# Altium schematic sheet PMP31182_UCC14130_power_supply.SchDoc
size A3; Date: Not shown in title block; ApprovedBy: Not shown in title block; CheckedBy: Not shown in title block; Author: Not shown in title block; CompanyName: Not shown in title block; Engineer: Not shown in title block; Organization: Not shown in title block; Address1: Not shown in title block; Address2: Not shown in title block; Address3: Not shown in title block; Address4: Not shown in title block; DocumentNumber: UCC14130-Q1; Revision: Use project parameter SCH_Rev; SheetNumber: 1; SheetTotal: 1; PageSetup: Record=PageOptions¦CenterHorizontal=True¦CenterVertical=True¦PrintScale=0.69¦XCorrection=1.00¦YCorrection=1.00¦PrintKind=0¦BorderSize=5000000¦LeftOffset=0¦BottomOffset=0¦Orientation=2¦PaperLength=1000¦PaperWidth=1000¦Scale=100¦PaperSource=15¦PrintQuality=600¦MediaType=1¦DitherType=10¦PaperKind=Letter¦PrintScaleMode=1
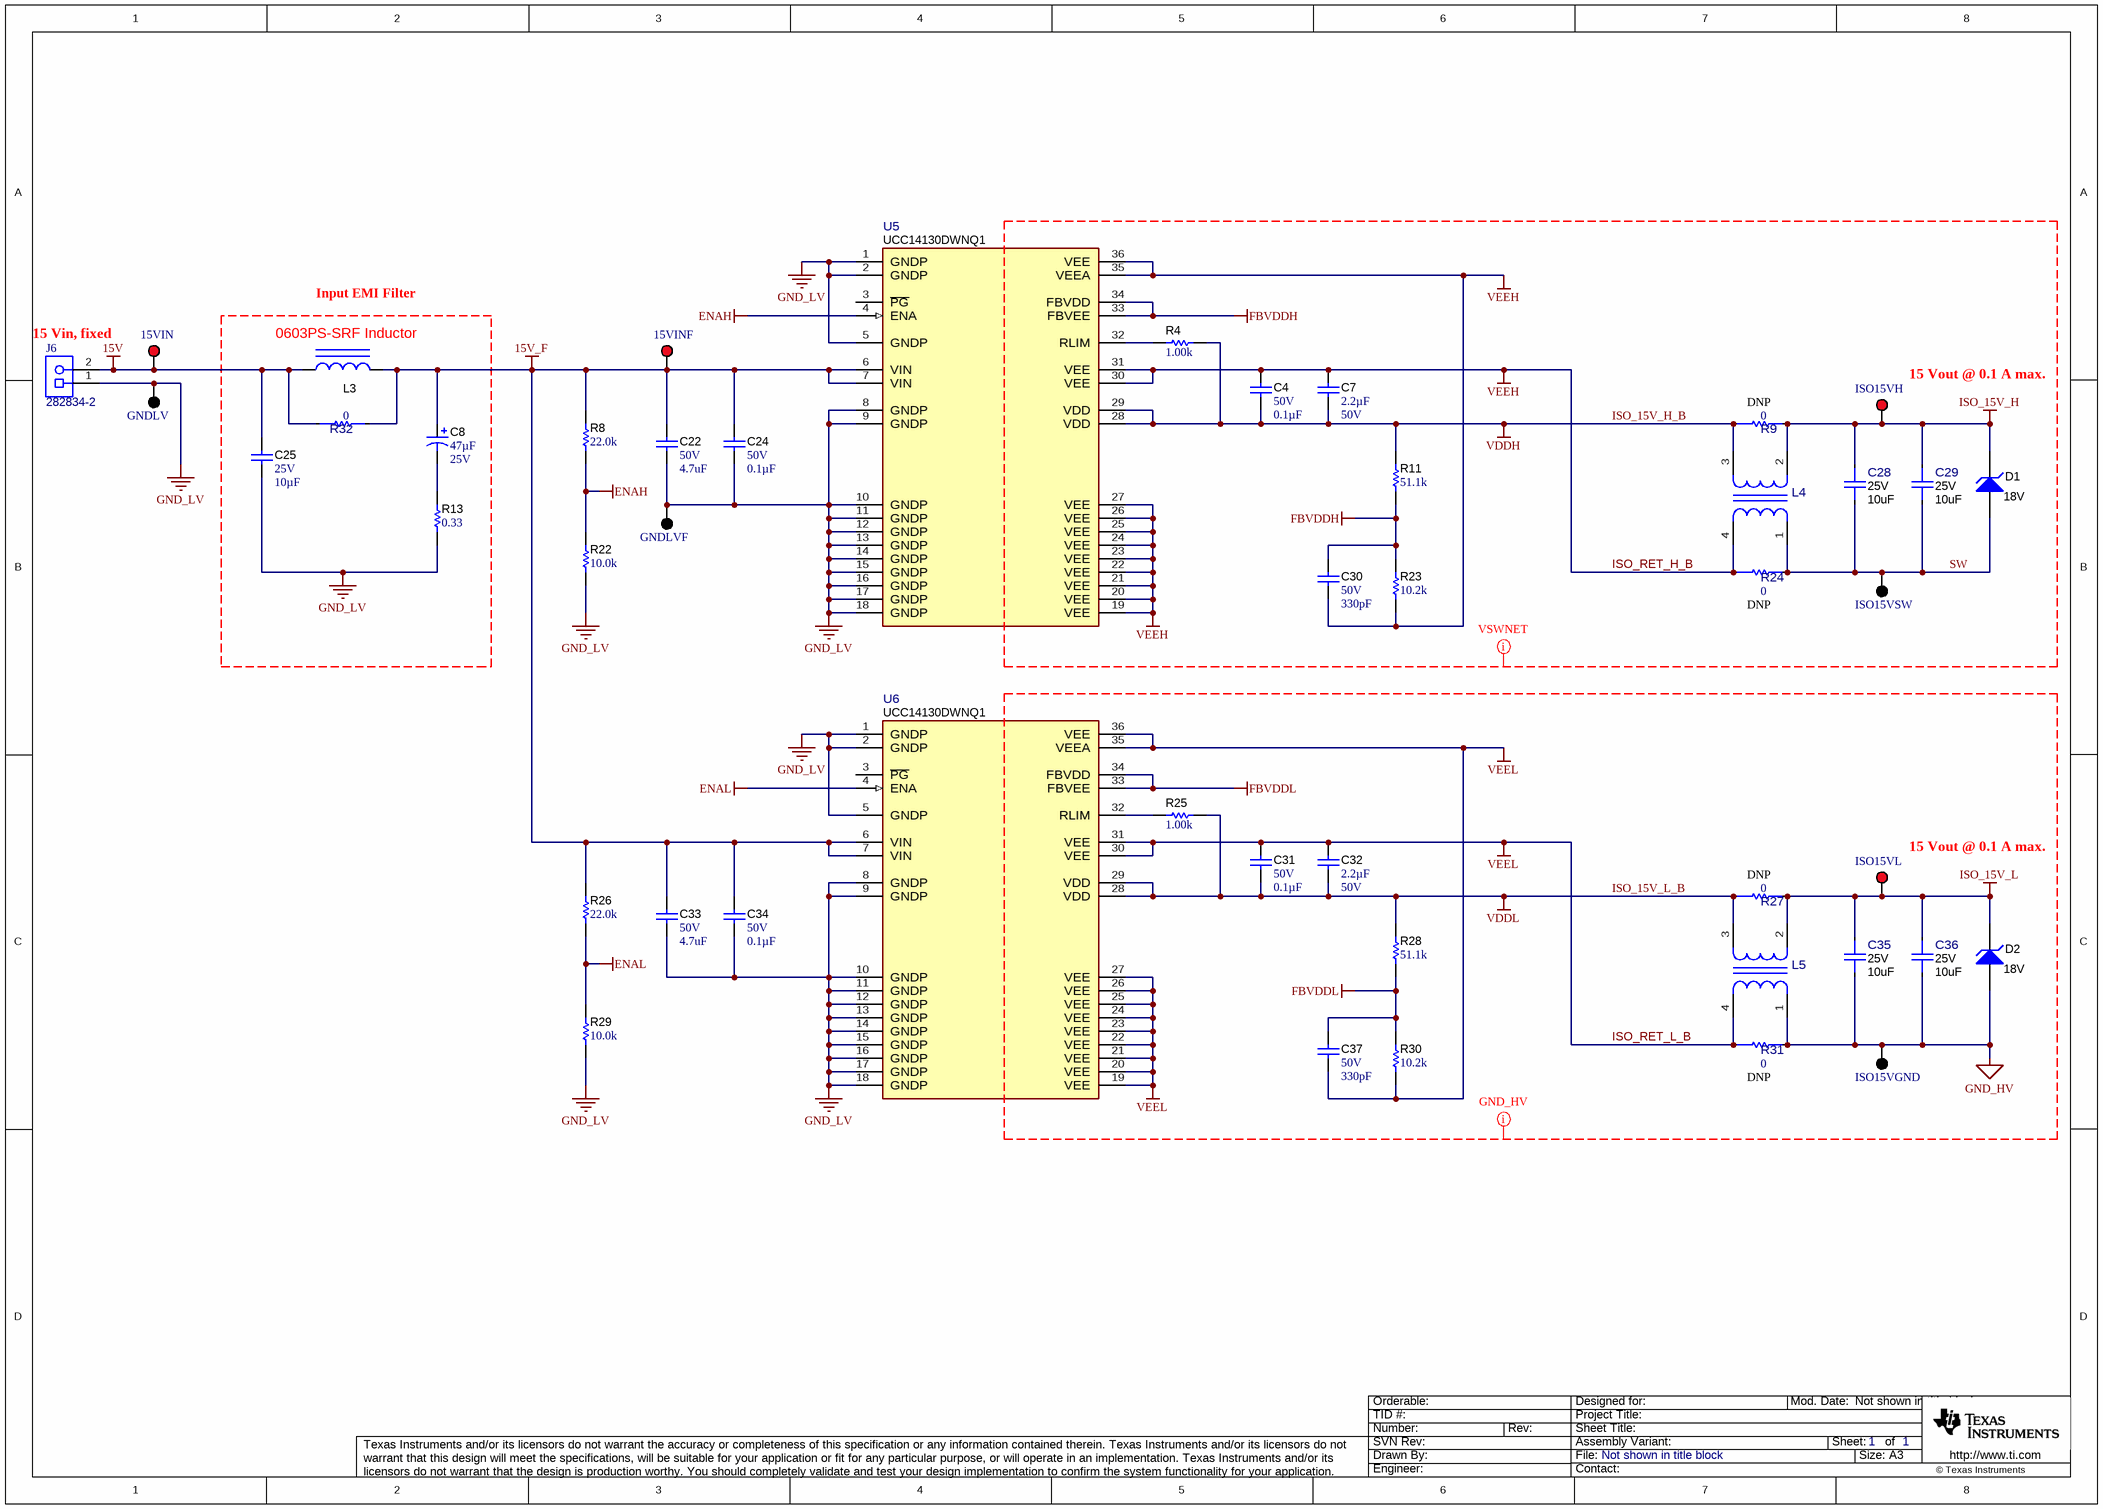
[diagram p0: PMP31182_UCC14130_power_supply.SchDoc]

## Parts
15VIN  5005  [Keystone5005]  (value not drawn)
15VINF  5005  [Keystone5005]  (value not drawn)
C4  VDC_V: 50V  ValueDisplayed: 0.1µF  [0603]  (hidden comment: CGA3E3X8R1H104K080AE)
C7  Cap_F: 2.2µF  VDC_V: 50V  [0805_HV]  (hidden comment: CGA4J3X7R1H225K125AB)
C8  ValueDisplayed: 47µF  VDC_V: 25V  [HXB_F61]  (hidden comment: HHXC250ARA470MF61G)
C22  VDC_V: 50V  ValueDisplayed: 4.7uF  [1210_280]  (hidden comment: CGA6P3X7R1H475M250AB)
C24  VDC_V: 50V  ValueDisplayed: 0.1µF  [0603]  (hidden comment: CGA3E3X8R1H104K080AE)
C25  VDC_V: 25V  ValueDisplayed: 10µF  [1206_180]  (hidden comment: C1206C106J3RACAUTO)
C28  VDC_V: 25V  ValueDisplayed: 10uF  [FP-CGA4J1X7S1E106K125AC_0805-MFG]  (hidden comment: CGA4J1X7S1E106K125AC)
C29  VDC_V: 25V  ValueDisplayed: 10uF  [FP-CGA4J1X7S1E106K125AC_0805-MFG]  (hidden comment: CGA4J1X7S1E106K125AC)
C30  VDC_V: 50V  ValueDisplayed: 330pF  [0603]  (hidden comment: 06035A331JAT2A)
C31  VDC_V: 50V  ValueDisplayed: 0.1µF  [0603]  (hidden comment: CGA3E3X8R1H104K080AE)
C32  Cap_F: 2.2µF  VDC_V: 50V  [0805_HV]  (hidden comment: CGA4J3X7R1H225K125AB)
C33  VDC_V: 50V  ValueDisplayed: 4.7uF  [1210_280]  (hidden comment: CGA6P3X7R1H475M250AB)
C34  VDC_V: 50V  ValueDisplayed: 0.1µF  [0603]  (hidden comment: CGA3E3X8R1H104K080AE)
C35  VDC_V: 25V  ValueDisplayed: 10uF  [FP-CGA4J1X7S1E106K125AC_0805-MFG]  (hidden comment: CGA4J1X7S1E106K125AC)
C36  VDC_V: 25V  ValueDisplayed: 10uF  [FP-CGA4J1X7S1E106K125AC_0805-MFG]  (hidden comment: CGA4J1X7S1E106K125AC)
C37  VDC_V: 50V  ValueDisplayed: 330pF  [0603]  (hidden comment: 06035A331JAT2A)
D1  value 18V  [SOD-123]  (hidden comment: BZT52C18-7-F)
D2  value 18V  [SOD-123]  (hidden comment: BZT52C18-7-F)
GNDLV  5006  [Keystone5006]  (value not drawn)
GNDLVF  5006  [Keystone5006]  (value not drawn)
ISO15VGND  5006  [Keystone5006]  (value not drawn)
ISO15VH  5005  [Keystone5005]  (value not drawn)
ISO15VL  5005  [Keystone5005]  (value not drawn)
ISO15VSW  5006  [Keystone5006]  (value not drawn)
J6  282834-2  [TEC_282834-2]
L3  0603PS-SRF Inductor  [0603AF]
L4  ACM2012-900-2P-T001  [FP-ACM2012-900-2P-T001_SMD4-MFG]  (value not drawn)
L5  ACM2012-900-2P-T001  [FP-ACM2012-900-2P-T001_SMD4-MFG]  (value not drawn)
R4  ValueDisplayed: 1.00k  [0603]  (hidden comment: RT0603BRD071KL)
R8  ValueDisplayed: 22.0k  [0603]  (hidden comment: RC0603FR-0722KL)
R9  Res_ohm: 0  [FP-ERJ-3GEY0R00V_0603-MFG]  (hidden comment: ERJ-3GEY0R00V)
R11  ValueDisplayed: 51.1k  [0603]  (hidden comment: RT0603BRD0751K1L)
R13  ValueDisplayed: 0.33  [0603]  (hidden comment: ERJ-3RQFR33V)
R22  ValueDisplayed: 10.0k  [0603]  (hidden comment: ERJ-3EKF1002V)
R23  ValueDisplayed: 10.2k  [0603]  (hidden comment: RT0603DRE0710K2L)
R24  Res_ohm: 0  [FP-ERJ-3GEY0R00V_0603-MFG]  (hidden comment: ERJ-3GEY0R00V)
R25  ValueDisplayed: 1.00k  [0603]  (hidden comment: RT0603BRD071KL)
R26  ValueDisplayed: 22.0k  [0603]  (hidden comment: RC0603FR-0722KL)
R27  Res_ohm: 0  [FP-ERJ-3GEY0R00V_0603-MFG]  (hidden comment: ERJ-3GEY0R00V)
R28  ValueDisplayed: 51.1k  [0603]  (hidden comment: RT0603BRD0751K1L)
R29  ValueDisplayed: 10.0k  [0603]  (hidden comment: ERJ-3EKF1002V)
R30  ValueDisplayed: 10.2k  [0603]  (hidden comment: RT0603DRE0710K2L)
R31  Res_ohm: 0  [FP-ERJ-3GEY0R00V_0603-MFG]  (hidden comment: ERJ-3GEY0R00V)
R32  Res_ohm: 0  [FP-ERJ-3GEY0R00V_0603-MFG]  (hidden comment: ERJ-3GEY0R00V)
U5  PartNumber: UCC14130DWNQ1  [DWN0036-MFG]  (hidden comment: UCC14240DWNQ1)
U6  PartNumber: UCC14130DWNQ1  [DWN0036-MFG]  (hidden comment: UCC14240DWNQ1)

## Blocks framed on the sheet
Input EMI Filter: C8 C25 L3 R13 R32

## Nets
15V: 15VIN.1 C25.1 J6.2 L3.1 R32.1
15V_F: 15VINF.1 C8.1(+) C22.1 C24.1 C33.1 C34.1 L3.2 R8.2 R26.2 R32.2 U5.6(VIN) U5.7(VIN) U6.6(VIN) U6.7(VIN)
ENAH: R8.1 R22.2 U5.4(ENA)
ENAL: R26.1 R29.2 U6.4(ENA)
FBVDDH: C30.1 R11.1 R23.2 U5.33(FBVEE) U5.34(FBVDD)
FBVDDL: C37.1 R28.1 R30.2 U6.33(FBVEE) U6.34(FBVDD)
GND_HV: C35.2 C36.2 D2.2(A) ISO15VGND.1 L5.1 R31.2
GND_LV: C22.2 C24.2 C25.2 C33.2 C34.2 GNDLV.1 GNDLVF.1 J6.1 R13.1 R22.1 R29.1 U5.1(GNDP) U5.2(GNDP) U5.5(GNDP) U5.8(GNDP) U5.9(GNDP) U5.10(GNDP) U5.11(GNDP) U5.12(GNDP) U5.13(GNDP) U5.14(GNDP) U5.15(GNDP) U5.16(GNDP) U5.17(GNDP) U5.18(GNDP) U6.1(GNDP) U6.2(GNDP) U6.5(GNDP) U6.8(GNDP) U6.9(GNDP) U6.10(GNDP) U6.11(GNDP) U6.12(GNDP) U6.13(GNDP) U6.14(GNDP) U6.15(GNDP) U6.16(GNDP) U6.17(GNDP) U6.18(GNDP)
ISO_15V_H: C28.1 C29.1 D1.1(K) ISO15VH.1 L4.2 R9.2
ISO_15V_H_B: C4.2 C7.2 L4.3 R4.2 R9.1 R11.2 U5.28(VDD) U5.29(VDD)  [also labelled VDDH]
ISO_15V_L: C35.1 C36.1 D2.1(K) ISO15VL.1 L5.2 R27.2
ISO_15V_L_B: C31.2 C32.2 L5.3 R25.2 R27.1 R28.2 U6.28(VDD) U6.29(VDD)  [also labelled VDDL]
ISO_RET_H_B: C4.1 C7.1 C30.2 L4.4 R23.1 R24.1 U5.19(VEE) U5.20(VEE) U5.21(VEE) U5.22(VEE) U5.23(VEE) U5.24(VEE) U5.25(VEE) U5.26(VEE) U5.27(VEE) U5.30(VEE) U5.31(VEE) U5.35(VEEA) U5.36(VEE)  [also labelled VEEH]
ISO_RET_L_B: C31.1 C32.1 C37.2 L5.4 R30.1 R31.1 U6.19(VEE) U6.20(VEE) U6.21(VEE) U6.22(VEE) U6.23(VEE) U6.24(VEE) U6.25(VEE) U6.26(VEE) U6.27(VEE) U6.30(VEE) U6.31(VEE) U6.35(VEEA) U6.36(VEE)  [also labelled VEEL]
SW: C28.2 C29.2 D1.2(A) ISO15VSW.1 L4.1 R24.2
NetC8_2: C8.2(-) R13.2
NetR4_1: R4.1 U5.32(RLIM)
NetR25_1: R25.1 U6.32(RLIM)

Not connected (* = marked no-connect by the designer): U5 3(~{PG}); U6 3(~{PG})

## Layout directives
net class VSWNET: FBVDDH, ISO_15V_H, ISO_15V_H_B, ISO_RET_H_B, SW, VDDH, VEEH
net class PGND: FBVDDL, GND_HV, ISO_15V_L, ISO_15V_L_B, ISO_RET_L_B, VDDL, VEEL

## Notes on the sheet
- 15 Vin, fixed
- (near ISO15VH) 15 Vout @ 0.1 A max.
- (near R9) DNP
- (near R24) DNP
- (near ISO15VL) 15 Vout @ 0.1 A max.
- (near R27) DNP
- (near R31) DNP

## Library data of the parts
15VIN = CMP-0055142-2: Test Point, Compact, Red, TH; Manufacturer: Keystone Electronics; CNHeader: FALSE; Green_Lifecycle: Active; Green_REACh: Passed; ContactFinish: Silver; CT: TRUE
15VINF ISO15VH ISO15VL = CMP-0055142-1: Test Point, Compact, Red, TH; Manufacturer: Keystone; CNHeader: FALSE; Green_Lifecycle: Active; Green_REACh: Passed; ContactFinish: Silver; CT: TRUE
C4 C24 C31 C34 = CMP-0079911-1: CAP, CERM, 0.1 µF, 50 V,+/- 10%, X8R, AEC-Q200 Grade 0, 0603; Manufacturer: TDK; Cap_F: 100nF; SizeAreaWB_mm2: 4.68; SizeArea_mm2: 1.28; AEC Qualified: Y; AEC Category: Q200; Value: 0.1uF; TaMax_C: 150°C; SizeZ_mm: 1; AEC Grade: 0; Polarized: N; TaMin_C: -55°C; SizeY_mm: 0.8; U/M: EA; SizeX_mm: 1.6
C7 C32 = CMP-0007977-2: CAP, CERM, 2.2 uF, 50 V, +/- 10%, X7R, AEC-Q200 Grade 1, 0805; Manufacturer: TDK; TaMin_C: -55°C; ESR_ohm: 3.288m; Polarized: N; SizeAreaWB_mm2: 6.75; Value1: 0.003288 ohm; U/M: EA; Value: 2.2uF; TaMax_C: 125°C; SizeZ_mm: 1.45; SizeX_mm: 2; SizeY_mm: 1.25; Cap_Case: 0805; SizeArea_mm2: 2.5; AEC Qualified: Y; IRMS_A: 3.60029A; AEC Grade: 1; AEC Category: Q200
C8 = CMP-0750159-1: CAP, AL, 47 µF, 25 V, +/- 20%, 0.05 ohm, AEC-Q200 Grade 1, SMD; Manufacturer: Chemi-Con; TaMin_C: -55°C; Cap_Case: 6.3x5.8mm; CompType: Capacitor; TaMax_C: 125°C; U/M: EA; Value: 47uF; AEC Grade: 1; AEC Category: Q200; AEC Qualified: Y; ESR_ohm: 0.05
C22 C33 = CMP-0009163-2: CAP, CERM, 4.7 uF, 50 V, +/- 20%, X7R, AEC-Q200 Grade 1, 1210; Manufacturer: TDK; TaMin_C: -55°C; Polarized: N; SizeAreaWB_mm2: 14.7; Value1: Unknown; U/M: EA; Value: 4.7uF; TaMax_C: 125°C; SizeZ_mm: 2.8; SizeX_mm: 3.2; SizeY_mm: 2.5; Cap_Case: 1210; SizeArea_mm2: 8; AEC Qualified: Y; Cap_F: 4.7µF; AEC Grade: 1; AEC Category: Q200
C25 = CMP-0081062-1: CAP, CERM, 10 µF, 25 V,+/- 5%, X7R, AEC-Q200 Grade 1, 1206; Manufacturer: Kemet; TaMin_C: -55°C; Polarized: N; SizeAreaWB_mm2: 10.92; U/M: EA; Value: 10uF; TaMax_C: 125°C; SizeZ_mm: 1.8; SizeX_mm: 3.2; SizeY_mm: 1.6; SizeArea_mm2: 5.12; AEC Qualified: Y; AEC Grade: 1; AEC Category: Q200
C28 C29 C35 C36 = CMP-0091069-1: Cap Ceramic 10uF 25V X7S 10% Pad SMD 0805 +125°C Automotive T/R; Manufacturer: TDK Corporation; AEC Qualified: Yes; AEC Grade: Grade 1; Value: 10µF; Tolerance_%: 0.1%; SizeZ_mm: 1.45mm; TempCo: 22%
C30 C37 = CMP-0006784-4: CAP, CERM, 330 pF, 50 V, +/- 5%, C0G/NP0, 0603; Manufacturer: AVX; TaMin_C: -55°C; ESR_ohm: 0.071; Polarized: N; SizeAreaWB_mm2: 4.68; Value1: 0.071 ohm; U/M: EA; Value: 330pF; TaMax_C: 125°C; SizeZ_mm: 1; SizeX_mm: 1.6; SizeY_mm: 0.8; SizeArea_mm2: 1.28; AEC Category: Q200
D1 D2 = CMP-0084402-3: Diode, Zener, 18 V, 500 mW, AEC-Q101, SOD-123; Manufacturer: Diodes Inc.; SizeX_mm: 3.85; SizeAreaWB_mm2: 13.095; Green_REACh: Incomplete; AEC Category: Q101; AEC Qualified: Y; Value1: 0.5W; SizeY_mm: 1.7; Power_W: 500mW; SizeZ_mm: 1.35; RJA_CperW: 338; SizeArea_mm2: 6.545; Green_Lifecycle: Active
GNDLV GNDLVF ISO15VGND ISO15VSW = CMP-0055143-1: Test Point, Compact, Black, TH; Manufacturer: Keystone; CNHeader: FALSE; Green_Lifecycle: Active; Green_REACh: Passed; ContactFinish: Silver; CT: TRUE
J6 = CMP-0054974-1: Terminal Block, 2x1, 2.54mm, TH; Manufacturer: TE Connectivity; CNHeader: FALSE; Green_Lifecycle: Active; Green_REACh: Passed; CT: TRUE
L3 = CMP-0060122-1: Inductor, Wirewound, Ferrite, 240 nH, 0.85 A, 0.119999 ohm, SMD; Manufacturer: Coilcraft; PartNumber: 0603AF-241KRB; Irms: 0.85A @ 15C rise; Green_Lifecycle: Not Set; SizeAreaWB_mm2: 5.936; DCR_ohm: 1.19999d; Green_REACh: Incomplete; Value: 240nH; Imax_A: 8.5dA; SizeZ_mm: 0.91; SizeX_mm: 1.8; SizeY_mm: 1.12; Value2: 0.85A; SizeArea_mm2: 2.016; AEC Category: Q200
L4 L5 = CMP-0090488-1: 2 Line Common Mode Choke Surface Mount 90 Ohms @ 100MHz 400mA DCR 190mOhm; Manufacturer: TDK; SizeZ_mm: 1.3mm; DCR_ohm: 0.19; AEC Qualified: Yes; AEC Grade: Grade 2; Impedance At Frequency: 90Ω @ 100MHz
R4 R25 = CMP-0023919-2: RES, 1.00 k, 0.1%, 0.1 W, 0603; Manufacturer: Yageo America; Power_W: 100mW; TempCo: 25 ppm/C; Value_Code: 1k00; U/M: EA; Value: 1.00k; EIA_Code: E192; Res_ohm: 1k; SizeX_mm: 1.6; SizeY_mm: 0.8; SizeZ_mm: 1; Value2: 0.1W; SizeArea_mm2: 1.28; VDC_V: 75V; AEC Category: Q200
R8 R26 = CMP-0022925-5: RES, 22.0 k, 1%, 0.1 W, 0603; Manufacturer: Yageo; Power_W: 100mW; TempCo: 100 ppm/C; Value_Code: 22k0; Value: 22.0k; Res_ohm: 22k; SizeX_mm: 1.6; SizeY_mm: 0.8; SizeZ_mm: 1; Value2: 0.1W; SizeArea_mm2: 1.28; AEC Qualified: N; VDC_V: 75V; AEC Category: Q200; SizeAreaWB_mm2: 4.68
R9 R24 R27 R31 R32 = CMP-0089143-1: 0 Ohms Jumper 0.1W, 1/10W Chip Resistor 0603 (1608 Metric) Automotive AEC-Q200 Thick Film; Manufacturer: Panasonic; SizeZ_mm: 0.55mm; AEC Grade: Grade 0; VDC_V: 75V; TempCo: -100/+600ppm/°C; AEC Qualified: Yes; Power_W: 100mW; Tolerance_%: 5%
R11 R28 = CMP-0024313-3: RES, 51.1 k, 0.1%, 0.1 W, 0603; Manufacturer: Yageo America; Power_W: 100mW; TempCo: 25 ppm/C; Value_Code: 51k1; U/M: EA; Value: 51.1k; EIA_Code: E192; SizeX_mm: 1.6; SizeY_mm: 0.8; SizeZ_mm: 1; Value2: 0.1W; SizeArea_mm2: 1.28; VDC_V: 75V; AEC Category: Q200
R13 = CMP-0022714-3: RES, 0.33, 1%, 0.1 W, AEC-Q200 Grade 0, 0603; Manufacturer: Panasonic; Power_W: 100mW; TempCo: 300 ppm/C; Value_Code: R330; Value: 0.33; EIA_Code: E96; SizeX_mm: 1.6; SizeY_mm: 0.8; SizeZ_mm: 1; Value2: 0.1W; SizeArea_mm2: 1.28; AEC Qualified: Y; AEC Category: Q200; AEC Grade: 0; SizeAreaWB_mm2: 4.68
R22 R29 = CMP-0022684-3: RES, 10.0 k, 1%, 0.1 W, 0603; Manufacturer: Panasonic; Power_W: 100mW; TempCo: 100 ppm/C; Value_Code: 10k0; U/M: EA; Value: 10.0k; EIA_Code: E96; Res_ohm: 10k; SizeX_mm: 1.6; SizeY_mm: 0.8; SizeZ_mm: 1; Value2: 0.1W; SizeArea_mm2: 1.28; VDC_V: 75V; AEC Category: Q200
R23 R30 = CMP-0024580-3: RES, 10.2 k, 0.5%, 0.1 W, 0603; Manufacturer: Yageo America; Power_W: 100mW; TempCo: 50 ppm/C; Value_Code: 10k2; U/M: EA; Value: 10.2k; EIA_Code: E192; SizeX_mm: 1.6; SizeY_mm: 0.8; SizeZ_mm: 1; Value2: 0.1W; SizeArea_mm2: 1.28; VDC_V: 75V; AEC Category: Q200
U5 U6 = CMP-0089786-7: 2W, 24V-Vin, 25V-Vout, High-Efficiency, 5 kVRMS Isolated DC-DC Converter; Manufacturer: Texas Instruments; Max Supply Voltage: 27V; Standoff Height: 0.1mm; SizeZ_mm: 3.55mm; AEC Qualified: Yes; Output Voltage: 18-25/2.5-25V; TaMin_C: -40°C; CompType: IC; TJmax_C: +150°C; Min Supply Voltage: 21V; AEC Grade: Grade 1; Number Of Outputs: 2; Output Type: AdjustableProgrammable; TaMax_C: +125°C; AEC Category: Q200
